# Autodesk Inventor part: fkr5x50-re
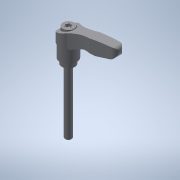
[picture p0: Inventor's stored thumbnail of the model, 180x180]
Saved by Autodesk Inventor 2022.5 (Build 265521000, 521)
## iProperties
Created: 2016-12
Part Number: fkr5x50-re
Material: 一般
Document SubType Name: Modeling
Designer: imaocorp
Density: 1 g/cm^3
Appearance: 既定
Author: imaocorp
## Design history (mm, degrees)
node "fkr5x50-re.x_t1"
node "K1000_105050_012"
node "Base1"
